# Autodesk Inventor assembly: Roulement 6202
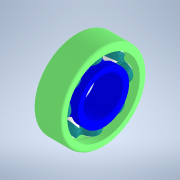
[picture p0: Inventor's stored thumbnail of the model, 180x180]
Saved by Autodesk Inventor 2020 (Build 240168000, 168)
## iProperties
Created: 2003-06
Part Number: Roulement 6202
Document SubType Name: Assembly
Designer: Bruno
Author: Bruno
Sending System: SolidWorks 2011
Last Author: Professeur
Last Saved: 2014-11-10
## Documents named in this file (5)
- D:\Téléchargements-2016-17\scoot_elec\pièces à assembler\ROULEMENT 6202\Roulement 6202.iam
- D:\Téléchargements-2016-17\scoot_elec\pièces à assembler\ROULEMENT 6202\Bague intérieure 6202.ipt
- D:\Téléchargements-2016-17\scoot_elec\pièces à assembler\ROULEMENT 6202\Billes 6202.ipt
- D:\Téléchargements-2016-17\scoot_elec\pièces à assembler\ROULEMENT 6202\Cage 6202.ipt
- D:\Téléchargements-2016-17\scoot_elec\pièces à assembler\ROULEMENT 6202\Bague extérieure 6202.ipt
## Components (11 placed, 4 different names)
1. Bague intérieure 6202:1
2. Billes 6202:1
3. Cage 6202:1
4. Billes 6202:2
5. Billes 6202:3
6. Billes 6202:4
7. Billes 6202:5
8. Billes 6202:6
9. Billes 6202:7
10. Billes 6202:8
11. Bague extérieure 6202:1
